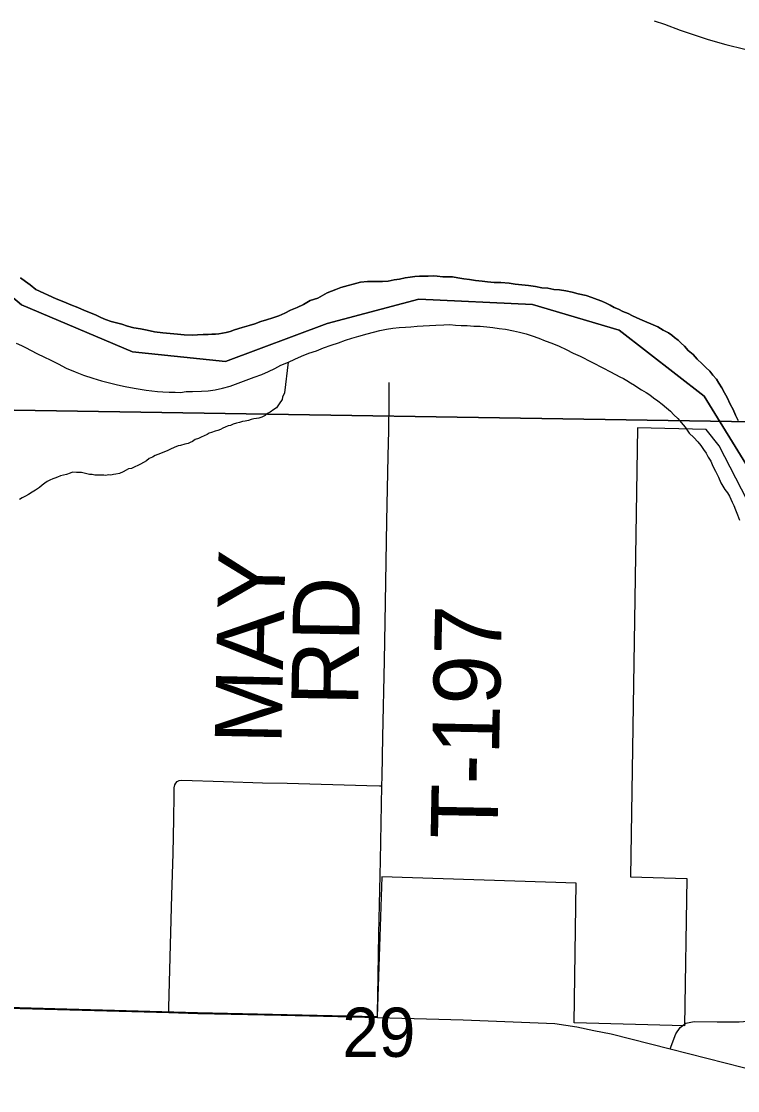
# Model space of a CAD drawing. Extents: x 0 to 34, y 0 to 22.
# Drawn here: x 2.609 to 3.218, y 17.91 to 18.819 of the extents above; entities that cross this region are included whole.
import ezdxf

# ---------------------------------------------------------------- set-up
doc = ezdxf.new("R2010")
doc.units = 0
for name, color, linetype in [('Default', 7, 'Continuous'), ('GM_X_City_Street', 7, 'Continuous'), ('GM_X_County_Road', 7, 'Continuous'), ('GM_X_Major_River', 7, 'Continuous'), ('GM_X_Minor_River', 7, 'Continuous'), ('GM_X_Section', 7, 'Continuous'), ('GM_X_Section_Text', 7, 'Continuous'), ('GM_X_Township_Road', 7, 'Continuous'), ('GM_X_Township_Road_Text', 7, 'Continuous')]:
    doc.layers.add(name, color=color, linetype=linetype)

msp = doc.modelspace()

# ---------------------------------------------------------------- linework, layer by layer
at = {"layer": 'Default'}
msp.add_lwpolyline([(3.27318, 18.3207), (3.20227, 18.45831), (3.1913, 18.47207), (3.13302, 18.4734), (3.12683, 18.09159), (3.17494, 18.09033), (3.17291, 17.96502), (3.07895, 17.96746), (3.08083, 18.08626), (2.91537, 18.09177), (2.91161, 17.97265), (2.75889, 17.97621), (2.59724, 17.9807), (2.58994, 17.90248), (2.52139, 17.90396), (2.52354, 17.98259), (2.41008, 17.98546), (2.40822, 17.90584), (2.39997, 17.47863), (2.38488, 17.02657), (2.38399, 16.99985), (4.29581, 17.61729)], dxfattribs=at)
at = {"layer": 'GM_X_City_Street'}
msp.add_lwpolyline([(3.16071, 17.94533), (3.1655, 17.95831), (3.16921, 17.96361), (3.17397, 17.96723), (3.18121, 17.96871), (3.20061, 17.96854), (3.21935, 17.96854), (3.23826, 17.96986), (3.24779, 17.97314), (3.25536, 17.97791), (3.2621, 17.9835), (3.26867, 17.99106), (3.27344, 17.99863), (3.27673, 18.00833), (3.27887, 18.01611)], dxfattribs=at)
at = {"layer": 'GM_X_County_Road'}
msp.add_line((3.16071, 17.94533), (3.27116, 17.91737), dxfattribs=at)
for points in [[(2.59648, 17.98018), (2.59748, 17.98015), (2.73432, 17.97634)], [(2.73432, 17.97634), (2.75912, 17.97565), (2.82983, 17.97406), (2.89013, 17.97268), (2.91184, 17.9721)], [(2.91184, 17.9721), (2.98462, 17.97014), (3.06248, 17.96707)], [(3.06248, 17.96707), (3.0814, 17.96425), (3.09589, 17.96103), (3.11038, 17.95821), (3.16071, 17.94533)]]:
    msp.add_lwpolyline(points, dxfattribs=at)
at = {"layer": 'GM_X_Major_River'}
for points in [[(2.93964, 18.60158), (2.93545, 18.60093), (2.93048, 18.59991), (2.92591, 18.59927), (2.92094, 18.59826), (2.916, 18.598), (2.90954, 18.59779), (2.90346, 18.59795), (2.89737, 18.59734), (2.88054, 18.59283), (2.87632, 18.59104), (2.86903, 18.58819), (2.86095, 18.58384), (2.85443, 18.58172), (2.84903, 18.57844), (2.84365, 18.57592), (2.83789, 18.57341), (2.83289, 18.57088), (2.8279, 18.56873), (2.82292, 18.56696), (2.81756, 18.56519), (2.81258, 18.5638), (2.8076, 18.56203), (2.80263, 18.56064), (2.79689, 18.55888), (2.79037, 18.55677), (2.78654, 18.55535), (2.7831, 18.55468), (2.78005, 18.554), (2.77699, 18.55332), (2.77395, 18.55301), (2.77091, 18.55309), (2.76786, 18.55279), (2.76369, 18.5529), (2.75874, 18.55264), (2.75418, 18.55238), (2.74734, 18.55255), (2.74166, 18.55308), (2.73559, 18.55361), (2.72915, 18.55416), (2.72234, 18.55509), (2.71591, 18.55639), (2.71025, 18.55768), (2.70457, 18.55858), (2.69928, 18.55986), (2.69439, 18.5615), (2.68986, 18.56276), (2.68533, 18.56401), (2.68044, 18.56566), (2.67668, 18.56727), (2.67255, 18.56927), (2.66766, 18.5713), (2.66278, 18.57332), (2.65714, 18.57575), (2.65112, 18.57818), (2.6451, 18.58061), (2.63871, 18.58305), (2.62143, 18.59109), (2.6166, 18.59501), (2.61249, 18.59778), (2.60839, 18.60092)], [(2.60839, 18.60092), (2.61249, 18.59778), (2.6166, 18.59501), (2.62143, 18.59109), (2.63871, 18.58305), (2.6451, 18.58061), (2.65112, 18.57818), (2.65714, 18.57575), (2.66278, 18.57332), (2.66766, 18.5713), (2.67255, 18.56927), (2.67668, 18.56727), (2.68044, 18.56566), (2.68533, 18.56401), (2.68986, 18.56276), (2.69439, 18.5615), (2.69928, 18.55986), (2.70457, 18.55858), (2.71025, 18.55768), (2.71591, 18.55639), (2.72234, 18.55509), (2.72915, 18.55416), (2.73559, 18.55361), (2.74166, 18.55308), (2.74734, 18.55255), (2.75418, 18.55238), (2.75874, 18.55264), (2.76369, 18.5529), (2.76786, 18.55279), (2.77091, 18.55309), (2.77395, 18.55301), (2.77699, 18.55332), (2.78005, 18.554), (2.7831, 18.55468), (2.78654, 18.55535), (2.79037, 18.55677), (2.79689, 18.55888), (2.80263, 18.56064), (2.8076, 18.56203), (2.81258, 18.5638), (2.81756, 18.56519), (2.82292, 18.56696), (2.8279, 18.56873), (2.83289, 18.57088), (2.83789, 18.57341), (2.84365, 18.57592), (2.84903, 18.57844), (2.85443, 18.58172), (2.86095, 18.58384), (2.86903, 18.58819), (2.87632, 18.59104), (2.88054, 18.59283), (2.89737, 18.59734), (2.90346, 18.59795), (2.90954, 18.59779), (2.916, 18.598), (2.92094, 18.59826), (2.92591, 18.59927), (2.93048, 18.59991), (2.93545, 18.60093), (2.93964, 18.60158)], [(3.21845, 18.47978), (3.21628, 18.48439), (3.21412, 18.489), (3.21157, 18.49363), (3.20906, 18.49939), (3.20688, 18.50324), (3.20471, 18.50747), (3.20214, 18.51134), (3.19995, 18.51481), (3.197, 18.51831), (3.19443, 18.52179), (3.19109, 18.52491), (3.18775, 18.52804), (3.18367, 18.53194), (3.18034, 18.53582), (3.17588, 18.53935), (3.17292, 18.54284), (3.16995, 18.54558), (3.16735, 18.54792), (3.16437, 18.55028), (3.16214, 18.55223), (3.15915, 18.55421), (3.15465, 18.5566), (3.15017, 18.55938), (3.13475, 18.56584), (3.12875, 18.56866), (3.125, 18.57065), (3.12048, 18.57229), (3.11673, 18.57428), (3.11297, 18.5759), (3.1096, 18.57788), (3.10623, 18.57948), (3.10247, 18.5811), (3.09871, 18.58272), (3.09419, 18.58435), (3.08929, 18.58599), (3.08249, 18.58731), (3.07721, 18.58896), (3.07192, 18.58985), (3.06662, 18.59075), (3.0617, 18.59125), (3.05678, 18.59214), (3.05148, 18.59265), (3.04618, 18.59355), (3.04013, 18.59446), (3.03444, 18.59499), (3.02876, 18.59551), (3.02384, 18.5964), (3.01664, 18.59696), (3.01094, 18.5971), (3.00526, 18.59763), (3.00071, 18.59813), (2.99503, 18.59865), (2.99011, 18.59953), (2.98519, 18.60004), (2.98027, 18.60092), (2.97573, 18.6018), (2.97118, 18.60191), (2.96738, 18.60201), (2.96246, 18.60252), (2.95904, 18.6026), (2.95485, 18.60233), (2.95106, 18.60243), (2.94764, 18.60252), (2.94346, 18.60224), (2.93964, 18.60158)], [(2.93964, 18.60158), (2.94346, 18.60224), (2.94764, 18.60252), (2.95106, 18.60243), (2.95485, 18.60233), (2.95904, 18.6026), (2.96246, 18.60252), (2.96738, 18.60201), (2.97118, 18.60191), (2.97573, 18.6018), (2.98027, 18.60092), (2.98519, 18.60004), (2.99011, 18.59953), (2.99503, 18.59865), (3.00071, 18.59813), (3.00526, 18.59763), (3.01094, 18.5971), (3.01664, 18.59696), (3.02384, 18.5964), (3.02876, 18.59551), (3.03444, 18.59499), (3.04013, 18.59446), (3.04618, 18.59355), (3.05148, 18.59265), (3.05678, 18.59214), (3.0617, 18.59125), (3.06662, 18.59075), (3.07192, 18.58985), (3.07721, 18.58896), (3.08249, 18.58731), (3.08929, 18.58599), (3.09419, 18.58435), (3.09871, 18.58272), (3.10247, 18.5811), (3.10623, 18.57948), (3.1096, 18.57788), (3.11297, 18.5759), (3.11673, 18.57428), (3.12048, 18.57229), (3.125, 18.57065), (3.12875, 18.56866), (3.13475, 18.56584), (3.15017, 18.55938), (3.15465, 18.5566), (3.15915, 18.55421), (3.16214, 18.55223), (3.16437, 18.55028), (3.16735, 18.54792), (3.16995, 18.54558), (3.17292, 18.54284), (3.17588, 18.53935), (3.18034, 18.53582), (3.18367, 18.53194), (3.18775, 18.52804), (3.19109, 18.52491), (3.19443, 18.52179), (3.197, 18.51831), (3.19995, 18.51481), (3.20214, 18.51134), (3.20471, 18.50747), (3.20688, 18.50324), (3.20906, 18.49939), (3.21157, 18.49363), (3.21412, 18.489), (3.21628, 18.48439), (3.21845, 18.47978)], [(2.60472, 18.54556), (2.60923, 18.54355), (2.61298, 18.54155), (2.61672, 18.53956), (2.62272, 18.53637), (2.62798, 18.53395), (2.63399, 18.53114), (2.64037, 18.52794), (2.64711, 18.52435), (2.65463, 18.52112), (2.66178, 18.51828), (2.66969, 18.5158), (2.67723, 18.51333), (2.68402, 18.51163), (2.69082, 18.50994), (2.69724, 18.50864), (2.70481, 18.5073), (2.7101, 18.50641), (2.71502, 18.50552), (2.71994, 18.50502), (2.72487, 18.50451), (2.72942, 18.50402), (2.73473, 18.50388), (2.73967, 18.50375), (2.74422, 18.50364), (2.74917, 18.50427), (2.7545, 18.50451), (2.7621, 18.5047), (2.7678, 18.50493), (2.77391, 18.50592), (2.78002, 18.50728), (2.78652, 18.50901), (2.80684, 18.51647), (2.81336, 18.51896), (2.81912, 18.52147), (2.8245, 18.524), (2.82951, 18.52691), (2.83603, 18.5294), (2.84141, 18.53192), (2.84717, 18.53443), (2.85331, 18.53693), (2.85982, 18.53905), (2.86596, 18.54155), (2.87247, 18.54366), (2.87861, 18.54578), (2.88474, 18.54791), (2.8901, 18.54967), (2.89584, 18.55142), (2.90311, 18.55352), (2.90846, 18.5549), (2.91382, 18.55628), (2.91954, 18.55727), (2.92488, 18.55828), (2.93021, 18.5589), (2.93554, 18.55914), (2.9401, 18.55941), (2.94544, 18.56003), (2.95076, 18.56028), (2.95609, 18.56052), (2.96141, 18.56076), (2.96825, 18.56097), (2.9732, 18.56122), (2.97812, 18.56072), (2.98306, 18.56059), (2.98799, 18.56047), (2.99368, 18.55994), (2.99899, 18.55981), (3.00468, 18.55928), (3.00998, 18.55877)], [(2.60472, 18.54556), (2.60923, 18.54355), (2.61298, 18.54155), (2.61672, 18.53956), (2.62272, 18.53637), (2.62798, 18.53395), (2.63399, 18.53114), (2.64037, 18.52794), (2.64711, 18.52435), (2.65463, 18.52112), (2.66178, 18.51828), (2.66969, 18.5158), (2.67723, 18.51333), (2.68402, 18.51163), (2.69082, 18.50994), (2.69724, 18.50864), (2.70481, 18.5073), (2.7101, 18.50641), (2.71502, 18.50552), (2.71994, 18.50502), (2.72487, 18.50451), (2.72942, 18.50402), (2.73473, 18.50388), (2.73967, 18.50375), (2.74422, 18.50364), (2.74917, 18.50427), (2.7545, 18.50451), (2.7621, 18.5047), (2.7678, 18.50493), (2.77391, 18.50592), (2.78002, 18.50728), (2.78652, 18.50901), (2.80684, 18.51647), (2.81336, 18.51896), (2.81912, 18.52147), (2.8245, 18.524), (2.82951, 18.52691), (2.83603, 18.5294), (2.84141, 18.53192), (2.84717, 18.53443), (2.85331, 18.53693), (2.85982, 18.53905), (2.86596, 18.54155), (2.87247, 18.54366), (2.87861, 18.54578), (2.88474, 18.54791), (2.8901, 18.54967), (2.89584, 18.55142), (2.90311, 18.55352), (2.90846, 18.5549), (2.91382, 18.55628), (2.91954, 18.55727), (2.92488, 18.55828), (2.93021, 18.5589), (2.93554, 18.55914), (2.9401, 18.55941), (2.94544, 18.56003), (2.95076, 18.56028), (2.95609, 18.56052), (2.96141, 18.56076), (2.96825, 18.56097), (2.9732, 18.56122), (2.97812, 18.56072), (2.98306, 18.56059), (2.98799, 18.56047), (2.99368, 18.55994), (2.99899, 18.55981), (3.00468, 18.55928), (3.00998, 18.55877)], [(3.00998, 18.55877), (3.01528, 18.55787), (3.02058, 18.55736), (3.02739, 18.55605), (3.03267, 18.55477), (3.03834, 18.55349), (3.04324, 18.55184), (3.04888, 18.5498), (3.05452, 18.54738), (3.06017, 18.54534), (3.06618, 18.5429), (3.07219, 18.54009), (3.07819, 18.5369), (3.08421, 18.53447), (3.10408, 18.52409), (3.10933, 18.52129), (3.11421, 18.51889), (3.11795, 18.5169), (3.12095, 18.5153), (3.12395, 18.5137), (3.12694, 18.51173), (3.13031, 18.50974), (3.1333, 18.50777), (3.13629, 18.5058), (3.14041, 18.50341), (3.1434, 18.50144), (3.14638, 18.49908), (3.15011, 18.49633), (3.15384, 18.49357), (3.15756, 18.49044), (3.1609, 18.4877), (3.16387, 18.48458), (3.16721, 18.48146), (3.17016, 18.47797), (3.17348, 18.47408), (3.17677, 18.46906), (3.18085, 18.46516), (3.18418, 18.46166), (3.18677, 18.45855), (3.18896, 18.45508), (3.19116, 18.45198), (3.19297, 18.44852), (3.19517, 18.44505), (3.19696, 18.44082), (3.19913, 18.43659), (3.20167, 18.43159), (3.20382, 18.42659), (3.2071, 18.42119), (3.2093, 18.4181), (3.21114, 18.41539), (3.21221, 18.41271), (3.21329, 18.4104), (3.21473, 18.40733), (3.21617, 18.40387), (3.21796, 18.39965), (3.21974, 18.39504)], [(3.00998, 18.55877), (3.01528, 18.55787), (3.02058, 18.55736), (3.02739, 18.55605), (3.03267, 18.55477), (3.03834, 18.55349), (3.04324, 18.55184), (3.04888, 18.5498), (3.05452, 18.54738), (3.06017, 18.54534), (3.06618, 18.5429), (3.07219, 18.54009), (3.07819, 18.5369), (3.08421, 18.53447), (3.10408, 18.52409), (3.10933, 18.52129), (3.11421, 18.51889), (3.11795, 18.5169), (3.12095, 18.5153), (3.12395, 18.5137), (3.12694, 18.51173), (3.13031, 18.50974), (3.1333, 18.50777), (3.13629, 18.5058), (3.14041, 18.50341), (3.1434, 18.50144), (3.14638, 18.49908), (3.15011, 18.49633), (3.15384, 18.49357), (3.15756, 18.49044), (3.1609, 18.4877), (3.16387, 18.48458), (3.16721, 18.48146), (3.17016, 18.47797), (3.17348, 18.47408), (3.17677, 18.46906), (3.18085, 18.46516), (3.18418, 18.46166), (3.18677, 18.45855), (3.18896, 18.45508), (3.19116, 18.45198), (3.19297, 18.44852), (3.19517, 18.44505), (3.19696, 18.44082), (3.19913, 18.43659), (3.20167, 18.43159), (3.20382, 18.42659), (3.2071, 18.42119), (3.2093, 18.4181), (3.21114, 18.41539), (3.21221, 18.41271), (3.21329, 18.4104), (3.21473, 18.40733), (3.21617, 18.40387), (3.21796, 18.39965), (3.21974, 18.39504)]]:
    msp.add_lwpolyline(points, dxfattribs=at)
at = {"layer": 'GM_X_Minor_River'}
msp.add_lwpolyline([(2.83587, 18.52934), (2.83272, 18.50328), (2.8311, 18.49952), (2.83068, 18.49763), (2.8283, 18.49389), (2.82594, 18.49054), (2.82363, 18.48908), (2.82053, 18.48688), (2.81822, 18.4858), (2.81628, 18.48395), (2.81358, 18.4825), (2.81091, 18.48181), (2.809, 18.48147), (2.80671, 18.48115), (2.80442, 18.48045), (2.80212, 18.47975), (2.79944, 18.47906), (2.79715, 18.47874), (2.79448, 18.47805), (2.7918, 18.47735), (2.78913, 18.47666), (2.78682, 18.47558), (2.78491, 18.47525), (2.78223, 18.47418), (2.7803, 18.47309), (2.77837, 18.472), (2.77608, 18.4713), (2.77378, 18.4706), (2.77071, 18.46954), (2.7688, 18.46883), (2.76687, 18.46773), (2.76457, 18.46666), (2.76188, 18.46559), (2.75957, 18.4645), (2.75689, 18.46343), (2.75457, 18.46197), (2.75264, 18.46088), (2.75073, 18.46017), (2.74805, 18.45948), (2.74423, 18.45844), (2.74232, 18.45811), (2.73886, 18.45668), (2.73579, 18.45524), (2.73348, 18.45416), (2.73157, 18.45345), (2.72505, 18.45095), (2.72274, 18.44987), (2.72043, 18.44841), (2.71774, 18.44734), (2.71541, 18.4455), (2.71272, 18.44405), (2.7104, 18.44259), (2.7081, 18.44151), (2.70541, 18.44044), (2.70271, 18.43899), (2.70005, 18.43868), (2.69812, 18.43759), (2.69543, 18.43614), (2.69235, 18.4347), (2.6893, 18.43402), (2.68739, 18.43368), (2.6851, 18.43336), (2.6832, 18.43341), (2.68092, 18.43309), (2.67902, 18.43314), (2.67674, 18.4332), (2.6737, 18.43327), (2.67143, 18.43333), (2.66916, 18.43377), (2.66688, 18.43383), (2.66461, 18.43427), (2.66235, 18.43508), (2.66008, 18.43552), (2.65781, 18.43558), (2.65591, 18.43563), (2.65249, 18.43571), (2.65057, 18.43501), (2.64751, 18.43394), (2.64483, 18.43325), (2.64216, 18.43256), (2.63985, 18.43148), (2.63755, 18.43078), (2.63564, 18.43007), (2.63333, 18.42899), (2.63102, 18.42791), (2.62909, 18.42644), (2.62676, 18.4246), (2.62444, 18.42276), (2.62096, 18.42057), (2.61826, 18.41874), (2.61518, 18.41692), (2.61248, 18.41547), (2.60978, 18.41402), (2.60747, 18.41256)], dxfattribs=at)
at = {"layer": 'GM_X_Section'}
for points in [[(3.45491, 19.46644), (3.42832, 18.47555), (2.42321, 18.49146), (2.44752, 19.48204)], [(3.42832, 18.47555), (3.40485, 17.45313), (2.39807, 17.47931), (2.42321, 18.49146)]]:
    msp.add_lwpolyline(points, close=True, dxfattribs=at)
at = {"layer": 'GM_X_Township_Road'}
for points in [[(7.49369, 20.9), (2.1, 20.9), (2.1, 18.40743), (2.13458, 18.42262), (2.18283, 18.47438), (2.21037, 18.53534), (2.21609, 18.56868), (2.21022, 18.7216), (2.22284, 18.76184), (2.26995, 18.79177), (2.32399, 18.78835), (2.40197, 18.75511), (2.48134, 18.69997), (2.54578, 18.63102), (2.60905, 18.57816), (2.70336, 18.53798), (2.78269, 18.52998), (2.8689, 18.56223), (2.94706, 18.58299), (3.04363, 18.57845), (3.11723, 18.55665), (3.1897, 18.50036), (3.30482, 18.31303)], [(3.14711, 18.81957), (3.15591, 18.81661), (3.16928, 18.81158), (3.19293, 18.80372), (3.20792, 18.79952), (3.22422, 18.79546)], [(3.30482, 18.31303), (3.1897, 18.50036), (3.11723, 18.55665), (3.04363, 18.57845), (2.94706, 18.58299), (2.8689, 18.56223), (2.78269, 18.52998), (2.70336, 18.53798), (2.60905, 18.57816), (2.54578, 18.63102), (2.48134, 18.69997), (2.40197, 18.75511), (2.32399, 18.78835), (2.26995, 18.79177), (2.22284, 18.76184), (2.21022, 18.7216), (2.21609, 18.56868), (2.21037, 18.53534), (2.18283, 18.47438), (2.13458, 18.42262), (2.1, 18.40743), (2.1, 14.1)], [(2.91555, 18.16914), (2.9157, 18.17706), (2.91632, 18.21063), (2.91766, 18.27529), (2.91852, 18.32503), (2.91979, 18.39404), (2.92079, 18.44937), (2.92146, 18.47112), (2.92184, 18.49437), (2.92185, 18.51201)], [(2.73432, 17.97634), (2.73443, 17.98037), (2.735, 18.00212), (2.73708, 18.07604), (2.73801, 18.11144), (2.73851, 18.14063), (2.73879, 18.16115), (2.73892, 18.16737), (2.73939, 18.1698), (2.74021, 18.17146), (2.74149, 18.17279), (2.74313, 18.17362), (2.74557, 18.17401), (2.78098, 18.17266), (2.8139, 18.17168), (2.83502, 18.17134), (2.90271, 18.16947), (2.91343, 18.16919), (2.91555, 18.16914)], [(2.91184, 17.9721), (2.91193, 17.97656), (2.91219, 17.99001), (2.91305, 18.04338), (2.91434, 18.10556), (2.91555, 18.16914)]]:
    msp.add_lwpolyline(points, dxfattribs=at)

# ---------------------------------------------------------------- texts
at = {"layer": 'GM_X_Section_Text'}
msp.add_text('29', height=0.041856, rotation=0.00001, dxfattribs=at).set_placement((2.88181, 17.93864))
at = {"layer": 'GM_X_Township_Road_Text'}
for s, rotation, p in [('MAY', 88.81888, (2.83016, 18.20421)), ('RD', 89.00935, (2.89531, 18.23666)), ('T-197', 88.88396, (3.01375, 18.12356))]:
    msp.add_text(s, height=0.056818, rotation=rotation, dxfattribs=at).set_placement(p)

doc.saveas('drawing.dxf')
